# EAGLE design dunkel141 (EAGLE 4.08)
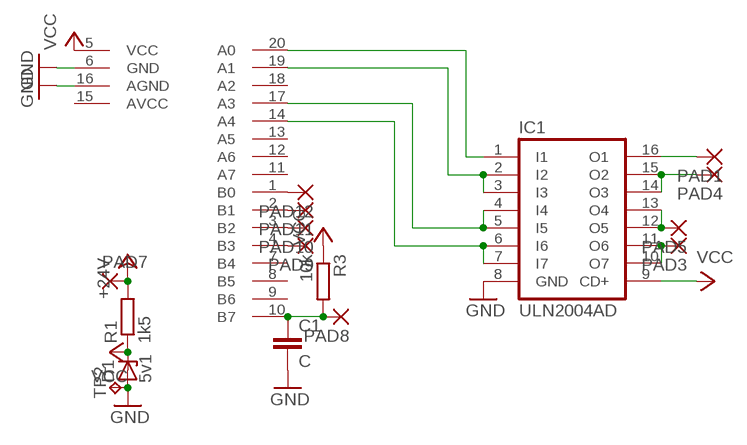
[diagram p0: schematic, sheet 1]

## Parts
C1  C  C-EUC1206  [C1206]
D1  5v1  ZENER-DIODESOD80C  [SOD80C]
IC1  ULN2004AD  [SO16]
PAD1  SMD2  [SMD2]
PAD3  SMD2  [SMD2]
PAD4  SMD2  [SMD2]
PAD5  SMD2  [SMD2]
PAD7  SMD2  [SMD2]
PAD8  SMD2  [SMD2]
PAD9  SMD2  [SMD2]
PAD10  SMD2  [SMD2]
PAD11  SMD2  [SMD2]
PAD12  SMD2  [SMD2]
R1  1k5  R-EU_R1206  [R1206]
R3  10k  R-EU_R1206  [R1206]
TP2  TP20SQ  [TP20SQ]
U$1  TINY26WIDE  [SOIC20S]

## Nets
+24V: PAD7.1(P) R1.2
GND: C1.2 D1.A IC1.8(GND) TP2.TP U$1.6(GND) U$1.16(AGND)
N$1: IC1.16(O1) PAD1.1(P)
N$3: IC1.12(O5) IC1.13(O4) PAD5.1(P)
N$4: IC1.14(O3) IC1.15(O2) PAD4.1(P)
N$5: IC1.10(O7) IC1.11(O6) PAD3.1(P)
N$6: PAD12.1(P) U$1.1(B0)
N$7: IC1.6(I6) IC1.7(I7) U$1.14(A4)
N$8: IC1.4(I4) IC1.5(I5) U$1.17(A3)
N$10: IC1.2(I2) IC1.3(I3) U$1.19(A1)
N$11: IC1.1(I1) U$1.20(A0)
N$12: PAD11.1(P) U$1.2(B1)
N$13: PAD10.1(P) U$1.3(B2)
N$14: PAD9.1(P) U$1.4(B3)
N$15: C1.1 PAD8.1(P) R3.2 U$1.10(B7)
VCC: D1.C IC1.9(CD+) R1.1 R3.1 U$1.5(VCC)
Unconnected: U$1.7(B4) U$1.8(B5) U$1.9(B6) U$1.11(A7) U$1.12(A6) U$1.13(A5) U$1.15(AVCC) U$1.18(A2)

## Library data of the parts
C1 = rcl:C-EU: CAPACITOR, European symbol
D1 = diode:ZENER-DIODE: Z-Diode
IC1 = uln-udn:ULN2004A: DRIVER ARRAY
PAD1 PAD3-PAD5 PAD7-PAD12 = wirepad:SMD2: SMD PAD
R1 R3 = rcl:R-EU_: RESISTOR, European symbol
TP2 = testpad:TP20SQ: TEST PIN
U$1 = avr:TINY26

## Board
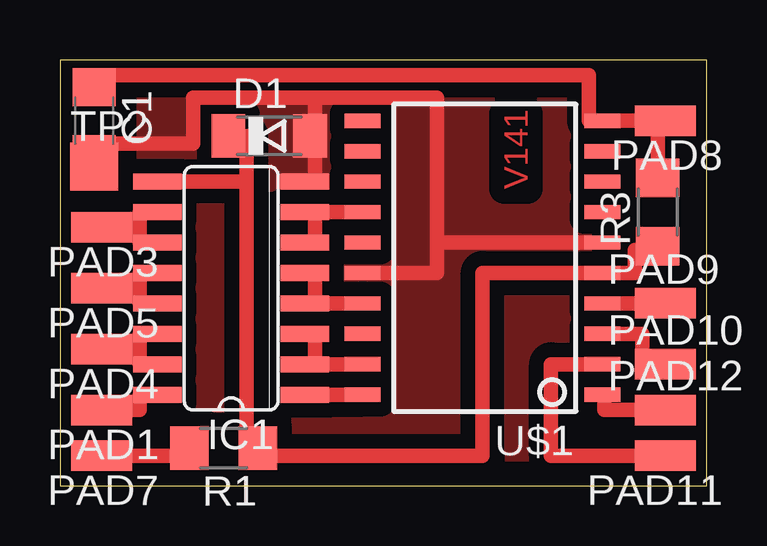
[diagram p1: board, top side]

Size 26.98 x 17.77 mm. Coordinates in mm from the lower left corner, seen from the top.
Outline: 0,0 26.98,0 26.98,17.77 0,17.77 0,0
Copper layers used: Top

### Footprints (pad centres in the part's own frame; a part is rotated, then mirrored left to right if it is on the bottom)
C1206 = smd 1.6 x 1.8: 1 -1.4,0; 2 1.4,0
SOD80C = smd 1.4 x 1.8: A 1.7,0; C -1.7,0
SO16 = smd 0.66 x 2.032: 1 -4.445,-3.073; 2 -3.175,-3.073; 3 -1.905,-3.073; 4 -0.635,-3.073; 5 0.635,-3.073; 6 1.905,-3.073; 7 3.175,-3.073; 8 4.445,-3.073; 9 4.445,3.073; 10 3.175,3.073; 11 1.905,3.073; 12 0.635,3.073; 13 -0.635,3.073; 14 -1.905,3.073; 15 -3.175,3.073; 16 -4.445,3.073
SMD2 = smd 1.27 x 2.54: 1 0,0
R1206 = smd 1.6 x 1.803: 1 -1.422,0; 2 1.422,0
TP20SQ = smd 2 x 2: TP 0,0
SOIC20S = smd 0.6 x 1.5: 1 -5.715,-5; 2 -4.445,-5; 3 -3.175,-5; 4 -1.905,-5; 5 -0.635,-5; 6 0.635,-5; 7 1.905,-5; 8 3.175,-5; 9 4.445,-5; 10 5.715,-5; 11 5.715,5; 12 4.445,5; 13 3.175,5; 14 1.905,5; 15 0.635,5; 16 -0.635,5; 17 -1.905,5; 18 -3.175,5; 19 -4.445,5; 20 -5.715,5

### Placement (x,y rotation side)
C1  1.42,15.23 270 top
D1  8.72,14.6 0 top
IC1  7.14,8.25 90 top
PAD1  1.74,3.17 90 top
PAD3  1.74,10.79 90 top
PAD4  1.74,5.71 90 top
PAD5  1.74,8.25 90 top
PAD7  1.74,1.27 90 top
PAD8  25.23,15.23 90 top
PAD9  25.23,7.62 270 top
PAD10  25.23,5.08 270 top
PAD11  25.23,1.27 90 top
PAD12  25.23,3.17 270 top
R1  6.82,1.58 180 top
R3  24.92,11.42 90 top
TP2  1.42,13.33 0 top
U$1  17.61,9.52 90 top

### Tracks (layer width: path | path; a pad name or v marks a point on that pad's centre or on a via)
+24V
  Top 0.61: 5.55,1.58 R1.2 5.23,1.58 5.23,1.27 1.42,1.27 1.42,0.95 PAD7.1
GND
  Top 0.406: TP2.TP C1.2
  Top 0.61: D1.A 10.63,14.6 10.63,12.69 | 15.71,8.88 15.71,10.15 U$1.6 22.7,10.15 | 10.63,12.69 IC1.8 | 10.63,16.19 5.55,16.19 5.55,14.28 1.74,14.28 C1.2 | 15.71,8.88 U$1.16 | 15.71,8.88 15.71,16.19 10.63,16.19 | 10.63,16.19 10.63,12.69
  pour Top (isolate 0.61, no thermals): 0.15,11.11 3.33,11.11 3.33,17.78 22.06,17.78 22.06,5.39 20.16,5.39 20.16,-0.01 7.77,-0.01 7.77,3.17 0.15,3.17
N$1
  Top 0.61: PAD1.1 3.33,3.17 3.33,3.81 IC1.16
N$3
  Top 0.61: PAD5.1 3.33,8.25 | IC1.12 3.33,8.88 3.33,8.25 | IC1.13 3.33,7.62 3.33,8.25
N$4
  Top 0.61: PAD4.1 3.33,5.71 | IC1.15 3.33,5.08 3.33,5.71 | IC1.14 3.33,6.34 3.33,5.71
N$5
  Top 0.61: PAD3.1 3.33,10.79 | 3.33,10.79 3.33,11.42 IC1.10 | IC1.11 3.33,10.15 3.33,10.79
N$6
  Top 0.406: U$1.1 22.7,3.81
  Top 0.61: 22.7,3.81 22.7,3.17 PAD12.1
N$7
  Top 0.61: IC1.6 10.63,10.15 10.63,11.42 IC1.7 U$1.14
N$8
  Top 0.61: 10.63,7.62 U$1.17 | IC1.5 10.63,8.88 10.63,7.62 | IC1.4 10.63,7.62
N$10
  Top 0.61: 10.63,5.08 U$1.19 | 10.63,5.08 IC1.2 | IC1.3 10.63,6.34 10.63,5.08
N$11
  Top 0.61: IC1.1 U$1.20
N$12
  Top 0.61: U$1.2 20.47,5.08 20.47,1.27 PAD11.1
N$13
  Top 0.61: U$1.3 24.28,6.34 24.28,4.76 PAD10.1
N$14
  Top 0.61: U$1.4 PAD9.1
N$15
  Top 0.61: 24.92,15.23 PAD8.1 | 24.92,15.23 R3.2 | 24.92,15.23 U$1.10 22.06,15.23 22.06,17.14 1.74,17.14 C1.1
VCC
  Top 0.61: IC1.9 7.77,12.69 7.77,12.38 | 7.77,12.38 7.77,14.6 D1.C | 7.77,1.27 7.77,12.38 | R3.1 24.6,10.15 24.92,10.15 24.92,9.84 23.96,9.84 23.96,8.88 U$1.5 17.61,8.88 17.61,1.27 7.77,1.27 | R1.1 7.77,1.27

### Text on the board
Top: V141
